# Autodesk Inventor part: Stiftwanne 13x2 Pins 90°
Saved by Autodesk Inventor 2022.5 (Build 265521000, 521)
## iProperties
Created: 2024-12
Part Number: Stiftwanne 13x2 Pins 90°
Material: Generic
Document SubType Name: Modeling
Designer: AdminForWorker
Density: 1 g/cm^3
Appearance: Default
Title: Stiftwanne 13x2 Pins 90°
Author: AdminForWorker
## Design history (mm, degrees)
feature "Body1"
body "Solid1"
